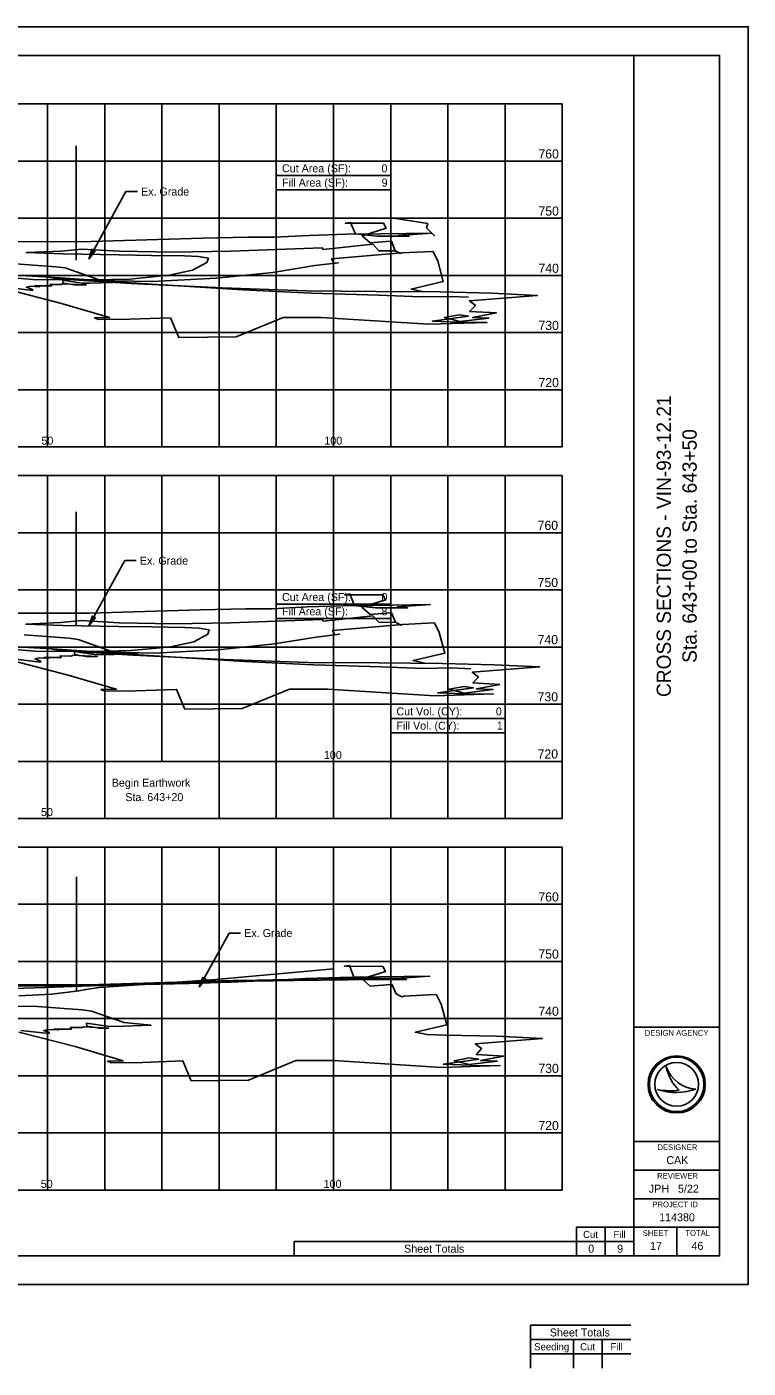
# Model space of a CAD drawing. Extents: x -46 to 154, y -27 to 78.
# Drawn here: x 116.94 to 129.55, y 54.21 to 77.68 of the extents above; entities that cross this region are included whole.
import ezdxf

# ---------------------------------------------------------------- set-up
doc = ezdxf.new("R2010")
doc.units = 0
for name, color, linetype in [('Default', 7, 'Continuous'), ('DT_P_Contour_Minor', 7, 'Continuous'), ('DT_X_Break_Line', 7, 'Continuous'), ('DT_X_Contour_Major', 7, 'Continuous'), ('DT_X_Contour_Minor', 7, 'Continuous'), ('DT_X_Spot_Elev', 7, 'Continuous'), ('DT_X_Void', 7, 'Continuous'), ('GE_P_Alignment_100_Stations', 7, 'Continuous'), ('HY_X_Water_Edge', 7, 'Continuous'), ('RD_X_Fence', 7, 'Continuous'), ('SH_Text', 7, 'Continuous'), ('XS_P_Pavt_Layers', 7, 'Continuous')]:
    doc.layers.add(name, color=color, linetype=linetype)

msp = doc.modelspace()

# ---------------------------------------------------------------- linework, layer by layer
at = {"layer": 'Default'}
for p, q in [((126.552, 56.178), (126.552, 56.678)), ((127.052, 56.178), (127.052, 56.678)), ((121.616, 56.178), (121.616, 56.428))]:
    msp.add_line(p, q, dxfattribs=at)
at = {"layer": 'DT_P_Contour_Minor'}
for p, q in [((118.674, 74.796), (118.022, 73.614)), ((118.874, 74.796), (118.674, 74.796)), ((118.022, 73.614), (118.085, 73.792)), ((118.138, 73.761), (118.022, 73.614)), ((118.085, 73.792), (118.085, 73.792)), ((118.138, 73.761), (118.138, 73.761)), ((118.655, 68.34), (118.026, 67.199)), ((118.855, 68.34), (118.655, 68.34)), ((118.026, 67.199), (118.089, 67.376)), ((118.142, 67.346), (118.026, 67.199)), ((118.089, 67.376), (118.089, 67.376)), ((118.142, 67.346), (118.142, 67.346)), ((120.478, 61.826), (119.956, 60.879)), ((120.678, 61.826), (120.478, 61.826)), ((119.956, 60.879), (120.018, 61.056)), ((120.072, 61.026), (119.956, 60.879)), ((120.018, 61.056), (120.018, 61.056)), ((120.072, 61.026), (120.072, 61.026))]:
    msp.add_line(p, q, dxfattribs=at)
for centre in [(118.135, 73.817), (118.139, 67.402), (120.068, 61.082)]:
    msp.add_arc(centre, 0.0563, 207.3099, 273.9906, dxfattribs=at)
at = {"layer": 'DT_X_Break_Line'}
for p, q in [((98.302, 76.328), (126.302, 76.328)), ((117.302, 70.328), (117.302, 76.328)), ((118.302, 70.328), (118.302, 76.328)), ((119.302, 70.328), (119.302, 76.328)), ((120.302, 70.328), (120.302, 76.328)), ((121.302, 70.328), (121.302, 76.328)), ((122.302, 70.328), (122.302, 76.328)), ((123.302, 70.328), (123.302, 76.328)), ((124.302, 70.328), (124.302, 76.328)), ((125.302, 70.328), (125.302, 76.328)), ((126.302, 70.328), (126.302, 76.328)), ((98.302, 75.328), (126.302, 75.328)), ((98.302, 74.328), (126.302, 74.328)), ((98.302, 73.328), (126.302, 73.328)), ((98.302, 72.328), (126.302, 72.328)), ((98.302, 71.328), (126.302, 71.328)), ((98.302, 70.328), (126.302, 70.328)), ((98.302, 69.828), (126.302, 69.828)), ((117.302, 63.828), (117.302, 69.828)), ((118.302, 63.828), (118.302, 69.828)), ((119.302, 64.828), (119.302, 69.828)), ((120.302, 63.828), (120.302, 69.828)), ((121.302, 63.828), (121.302, 69.828)), ((122.302, 63.828), (122.302, 69.828)), ((123.302, 63.828), (123.302, 69.828)), ((124.302, 63.828), (124.302, 69.828)), ((125.302, 63.828), (125.302, 69.828)), ((126.302, 63.828), (126.302, 69.828)), ((98.302, 68.828), (126.302, 68.828)), ((98.302, 67.828), (126.302, 67.828)), ((98.302, 66.828), (126.302, 66.828)), ((98.302, 65.828), (126.302, 65.828)), ((98.302, 64.828), (126.302, 64.828)), ((98.302, 63.828), (126.302, 63.828)), ((98.302, 63.328), (126.302, 63.328)), ((117.302, 57.328), (117.302, 63.328)), ((118.302, 57.328), (118.302, 63.328)), ((119.302, 57.328), (119.302, 63.328)), ((120.302, 57.328), (120.302, 63.328)), ((121.302, 57.328), (121.302, 63.328)), ((122.302, 57.328), (122.302, 63.328)), ((123.302, 57.328), (123.302, 63.328)), ((124.302, 57.328), (124.302, 63.328)), ((125.302, 57.328), (125.302, 63.328)), ((126.302, 57.328), (126.302, 63.328)), ((98.302, 62.328), (126.302, 62.328)), ((98.302, 61.328), (126.302, 61.328)), ((98.302, 60.328), (126.302, 60.328)), ((98.302, 59.328), (126.302, 59.328)), ((98.302, 58.328), (126.302, 58.328)), ((98.302, 57.328), (126.302, 57.328))]:
    msp.add_line(p, q, dxfattribs=at)
at = {"layer": 'DT_X_Contour_Major'}
msp.add_lwpolyline([(95.552, 55.678), (129.552, 55.678), (129.552, 77.678), (95.552, 77.678)], close=True, dxfattribs=at)
at = {"layer": 'DT_X_Contour_Minor'}
for p, q in [((121.302, 75.328), (123.302, 75.328)), ((121.302, 75.328), (121.302, 74.828)), ((123.302, 75.328), (123.302, 74.828)), ((121.302, 75.078), (123.302, 75.078)), ((121.302, 74.828), (123.302, 74.828)), ((121.302, 67.828), (123.302, 67.828)), ((121.302, 67.828), (121.302, 67.328)), ((123.302, 67.828), (123.302, 67.328)), ((121.302, 67.578), (123.302, 67.578)), ((121.302, 67.328), (123.302, 67.328)), ((123.302, 65.828), (125.302, 65.828)), ((123.302, 65.828), (123.302, 65.328)), ((125.302, 65.828), (125.302, 65.328)), ((123.302, 65.578), (125.302, 65.578)), ((123.302, 65.328), (125.302, 65.328)), ((128.119, 59.488), (128.119, 59.488)), ((128.119, 59.488), (128.119, 59.488)), ((128.302, 59.178), (128.302, 59.178)), ((127.969, 59.087), (127.969, 59.087)), ((127.969, 59.087), (127.969, 59.087)), ((128.639, 59.096), (128.639, 59.096)), ((128.639, 59.096), (128.639, 59.096)), ((126.552, 56.678), (127.552, 56.678)), ((128.302, 56.178), (128.302, 56.678)), ((121.616, 56.428), (127.552, 56.428)), ((125.749, 54.213), (125.749, 54.963)), ((125.749, 54.963), (127.499, 54.963)), ((125.749, 54.713), (127.499, 54.713)), ((126.499, 54.213), (126.499, 54.713)), ((126.999, 54.213), (126.999, 54.713)), ((125.749, 54.463), (127.499, 54.463)), ((126.131, 54.338), (126.131, 54.338)), ((126.754, 54.338), (126.754, 54.338)), ((127.259, 54.338), (127.259, 54.338))]:
    msp.add_line(p, q, dxfattribs=at)
for radius in [0.5, 0.5, 0.477, 0.477, 0.477, 0.477, 0.382, 0.382]:
    msp.add_circle((128.302, 59.178), radius, dxfattribs=at)
for centre, radius, start, end in [((128.668, 59.676), 0.58, 198.9257, 198.9319), ((128.898, 59.648), 0.796, 191.6379, 191.6421), ((128.668, 59.676), 0.58, 198.9257, 198.9319), ((128.898, 59.648), 0.796, 191.6379, 191.6421), ((128.668, 59.676), 0.58, 198.9319, 267.1657), ((128.898, 59.648), 0.796, 191.6421, 226.0947), ((128.668, 59.676), 0.58, 198.9319, 267.1657), ((128.898, 59.648), 0.796, 191.6421, 226.0947), ((128.291, 60.048), 1.013, 251.4576, 290.0832), ((128.291, 60.048), 1.013, 251.4576, 290.0832), ((128.2, 60.332), 1.266, 259.4964, 259.4995), ((128.291, 60.048), 1.013, 251.4527, 251.4576), ((128.2, 60.332), 1.266, 259.4995, 276.6672), ((128.2, 60.332), 1.266, 259.4964, 259.4995), ((128.291, 60.048), 1.013, 251.4527, 251.4576), ((128.2, 60.332), 1.266, 259.4995, 276.6672)]:
    msp.add_arc(centre, radius, start, end, dxfattribs=at)
at = {"layer": 'DT_X_Spot_Elev'}
for p, q in [((127.552, 56.178), (127.552, 77.178)), ((127.552, 60.178), (129.052, 60.178)), ((127.552, 58.178), (129.052, 58.178)), ((127.552, 57.678), (129.052, 57.678)), ((127.552, 57.178), (129.052, 57.178)), ((127.552, 56.678), (129.052, 56.678))]:
    msp.add_line(p, q, dxfattribs=at)
msp.add_lwpolyline([(97.052, 77.178), (129.052, 77.178), (129.052, 56.178), (97.052, 56.178)], close=True, dxfattribs=at)
at = {"layer": 'GE_P_Alignment_100_Stations'}
for p, q in [((117.802, 73.598), (117.802, 75.598)), ((117.805, 67.192), (117.805, 69.192)), ((117.809, 60.809), (117.809, 62.809))]:
    msp.add_line(p, q, dxfattribs=at)
at = {"layer": 'HY_X_Water_Edge'}
for points in [[(116.244, 73.328), (117.043, 73.257), (118.071, 73.25), (118.741, 73.265), (119.43, 73.333), (119.839, 73.421), (120.089, 73.553), (120.115, 73.631), (119.94, 73.658), (119.697, 73.671), (119.122, 73.679), (118.553, 73.69), (117.575, 73.706), (116.932, 73.728), (117.54, 73.756), (117.904, 73.79)], [(117.904, 73.79), (118.562, 73.754), (119.502, 73.736), (120.499, 73.752), (122.105, 73.81), (122.124, 73.781), (122.987, 73.874), (123.096, 73.76), (123.38, 73.761), (123.438, 73.728), (123.466, 73.712), (123.491, 73.723), (122.269, 73.618), (122.306, 73.543), (122.386, 73.552), (121.973, 73.5), (121.243, 73.383), (120.251, 73.281), (119.136, 73.22), (118.142, 73.243), (117.347, 73.29), (117.474, 73.27), (118.759, 73.187), (120.353, 73.11), (121.824, 73.06), (123.051, 73.05), (124.172, 73.041), (125.064, 73.02), (125.864, 72.98)], [(124.662, 72.949), (124.322, 72.962), (123.83, 72.955), (123.095, 72.982), (121.915, 73.017), (120.717, 73.076), (118.944, 73.185), (117.352, 73.299), (116.495, 73.343)], [(117.896, 67.29), (118.556, 67.254), (119.499, 67.236), (120.499, 67.252), (122.105, 67.31), (122.126, 67.281), (122.99, 67.374), (123.102, 67.26), (123.386, 67.261), (123.449, 67.228), (123.48, 67.212), (123.508, 67.223), (122.287, 67.118), (122.327, 67.043), (122.411, 67.052), (121.998, 67), (121.269, 66.883), (120.279, 66.781), (119.166, 66.72), (118.175, 66.743), (117.382, 66.79), (117.508, 66.77), (118.794, 66.687), (120.389, 66.61), (121.859, 66.56), (123.087, 66.55), (124.21, 66.541), (125.104, 66.52), (125.907, 66.48)], [(116.276, 66.828), (117.074, 66.757), (118.099, 66.75), (118.767, 66.765), (119.454, 66.833), (119.859, 66.921), (120.105, 67.053), (120.128, 67.131), (119.949, 67.158), (119.703, 67.171), (119.124, 67.179), (118.552, 67.19), (117.571, 67.206), (116.926, 67.228), (117.533, 67.256), (117.896, 67.29)], [(124.706, 66.449), (124.364, 66.462), (123.871, 66.455), (123.135, 66.482), (121.953, 66.517), (120.754, 66.576), (118.981, 66.685), (117.389, 66.799), (116.533, 66.843)], [(116.526, 60.904), (117.965, 60.9), (119.78, 60.945), (120.515, 60.966), (120.905, 60.982), (121.618, 60.994), (123.019, 61.015), (123.579, 61.014), (123.401, 61.029), (122.303, 61.028), (120.709, 60.996), (119.54, 60.947), (118.736, 60.917), (118.058, 60.904), (117.263, 60.872), (116.327, 60.843)], [(116.799, 60.728), (117.38, 60.756), (117.851, 60.813), (117.97, 60.838), (118.207, 60.874), (119.23, 60.943), (120.246, 61.012), (122.3, 61.2)]]:
    msp.add_lwpolyline(points, dxfattribs=at)
at = {"layer": 'RD_X_Fence'}
msp.add_lwpolyline([(123.315, 74.334), (123.95, 74.238), (123.929, 74.164), (124.076, 74.017)], dxfattribs=at)
at = {"layer": 'SH_Text'}
for points in [[(121.302, 75.328), (123.302, 75.328), (123.302, 74.828), (121.302, 74.828)], [(121.302, 67.828), (123.302, 67.828), (123.302, 67.328), (121.302, 67.328)], [(123.302, 65.828), (125.302, 65.828), (125.302, 65.328), (123.302, 65.328)]]:
    msp.add_lwpolyline(points, close=True, dxfattribs=at)
at = {"layer": 'XS_P_Pavt_Layers'}
for points in [[(116.653, 73.919), (118.066, 73.922), (120.01, 73.979), (120.804, 73.998), (121.264, 73.996), (121.875, 74.03), (122.684, 74.054), (123.066, 74.015), (123.623, 74.014), (123.441, 74.029), (124.019, 74.07), (122.688, 74.051), (122.602, 74.257), (122.51, 74.243), (123.176, 74.242), (123.221, 74.153), (122.801, 74.024), (122.943, 73.898), (123.3, 73.928), (123.314, 73.929), (123.38, 73.761), (123.438, 73.728), (123.466, 73.712), (123.491, 73.723), (124.031, 73.749), (124.046, 73.743), (124.127, 73.583), (124.222, 73.22), (123.659, 73.091), (123.861, 73.048), (124.172, 73.041), (125.064, 73.02), (125.864, 72.98), (124.679, 72.887), (124.784, 72.804), (124.682, 72.7), (125.149, 72.673), (124.734, 72.596), (125.016, 72.583), (124.511, 72.523), (124.241, 72.592), (124.501, 72.64), (124.662, 72.617), (124.031, 72.53), (124.493, 72.512), (124.548, 72.504), (124.988, 72.508), (123.963, 72.474), (122.088, 72.594), (121.422, 72.594), (120.598, 72.253), (119.598, 72.241), (119.451, 72.588), (118.743, 72.563), (118.196, 72.556), (118.126, 72.586), (118.386, 72.591), (117.549, 72.838), (116.56, 73.092)], [(116.565, 73.121), (117.043, 73.066), (117.041, 73.084), (116.932, 73.122), (117.006, 73.139), (117.163, 73.131), (117.078, 73.145), (117.372, 73.146), (117.346, 73.173), (117.541, 73.171), (117.558, 73.184), (117.978, 73.163), (117.813, 73.159), (117.574, 73.195), (117.562, 73.249), (117.91, 73.196), (118.03, 73.192), (118.65, 73.211), (118.185, 73.259), (117.611, 73.461), (117.45, 73.481), (116.667, 73.54)], [(116.62, 67.419), (118.033, 67.422), (119.978, 67.479), (120.772, 67.498), (121.23, 67.496), (121.84, 67.53), (122.648, 67.554), (123.04, 67.515), (123.598, 67.514), (123.418, 67.529), (123.998, 67.57), (122.671, 67.551), (122.59, 67.757), (122.499, 67.743), (123.166, 67.742), (123.214, 67.653), (122.799, 67.524), (122.941, 67.398), (123.3, 67.428), (123.316, 67.429), (123.386, 67.261), (123.449, 67.228), (123.48, 67.212), (123.508, 67.223), (124.054, 67.249), (124.071, 67.243), (124.152, 67.083), (124.25, 66.72), (123.694, 66.591), (123.898, 66.548), (124.21, 66.541), (125.104, 66.52), (125.907, 66.48), (124.727, 66.387), (124.835, 66.304), (124.74, 66.2), (125.21, 66.173), (124.801, 66.096), (125.088, 66.083), (124.589, 66.023), (124.323, 66.092), (124.586, 66.14), (124.749, 66.117), (124.124, 66.03), (124.591, 66.012), (124.65, 66.004), (125.097, 66.008), (124.072, 65.974), (122.196, 66.094), (121.531, 66.094), (120.705, 65.753), (119.705, 65.741), (119.558, 66.088), (118.849, 66.063), (118.302, 66.056), (118.237, 66.086), (118.503, 66.091), (117.665, 66.338), (116.677, 66.592)], [(116.698, 66.621), (117.181, 66.566), (117.185, 66.584), (117.081, 66.622), (117.161, 66.639), (117.323, 66.631), (117.243, 66.645), (117.543, 66.646), (117.522, 66.673), (117.723, 66.671), (117.745, 66.684), (118.171, 66.663), (118.011, 66.659), (117.778, 66.695), (117.771, 66.749), (118.125, 66.696), (118.249, 66.692), (118.877, 66.711), (118.411, 66.759), (117.837, 66.961), (117.677, 66.981), (116.894, 67.04)], [(116.592, 60.919), (118.006, 60.922), (119.951, 60.979), (120.745, 60.998), (121.202, 60.996), (121.81, 61.03), (122.619, 61.054), (123.019, 61.015), (123.579, 61.014), (123.401, 61.029), (123.983, 61.07), (122.66, 61.051), (122.584, 61.257), (122.494, 61.243), (123.162, 61.242), (123.213, 61.153), (122.802, 61.024), (122.946, 60.898), (123.305, 60.928), (123.324, 60.929), (123.397, 60.761), (123.464, 60.728), (123.499, 60.712), (123.531, 60.723), (124.082, 60.749), (124.102, 60.743), (124.183, 60.583), (124.284, 60.22), (123.734, 60.091), (123.94, 60.048), (124.254, 60.041), (125.15, 60.02), (125.955, 59.98), (124.78, 59.887), (124.892, 59.804), (124.802, 59.7), (125.278, 59.673), (124.873, 59.596), (125.165, 59.583), (124.672, 59.523), (124.411, 59.592), (124.676, 59.64), (124.842, 59.617), (124.223, 59.53), (124.693, 59.512), (124.757, 59.504), (125.211, 59.508), (124.186, 59.474), (122.31, 59.594), (121.646, 59.594), (120.817, 59.253), (119.816, 59.241), (119.669, 59.588), (118.961, 59.563), (118.413, 59.556), (118.353, 59.586), (118.624, 59.591), (117.787, 59.838), (116.798, 60.092)], [(116.837, 60.121), (117.325, 60.066), (117.334, 60.084), (117.236, 60.122), (117.321, 60.139), (117.489, 60.131), (117.414, 60.145), (117.719, 60.146), (117.704, 60.173), (117.91, 60.171), (117.938, 60.184), (118.37, 60.163), (118.214, 60.159), (117.987, 60.195), (117.986, 60.249), (118.345, 60.196), (118.474, 60.192), (119.109, 60.211), (118.643, 60.259), (118.07, 60.461), (117.909, 60.481), (117.126, 60.54), (115.911, 60.56)]]:
    msp.add_lwpolyline(points, dxfattribs=at)

# ---------------------------------------------------------------- texts
at = {"layer": 'Default'}
for s, height, p in [('Cut', 0.125, (126.666, 56.49)), ('Fill', 0.125, (127.196, 56.49)), ('Sheet Totals', 0.14, (123.537, 56.233)), ('0', 0.14, (126.756, 56.233)), ('9', 0.14, (127.261, 56.233))]:
    msp.add_text(s, height=height, dxfattribs=at).set_placement(p)
at = {"layer": 'DT_P_Contour_Minor'}
for p in [(118.937, 74.726), (118.918, 68.27), (120.741, 61.756)]:
    msp.add_text('Ex. Grade', height=0.14, dxfattribs=at).set_placement(p)
at = {"layer": 'DT_X_Contour_Minor'}
for s, p in [('CROSS SECTIONS - VIN-93-12.21', (128.202, 65.954)), ('Sta. 643+00 to Sta. 643+50', (128.652, 66.551))]:
    msp.add_text(s, height=0.25, rotation=90, dxfattribs=at).set_placement(p)
for s, height, p in [('DESIGN AGENCY', 0.1, (127.743, 60.028)), ('DESIGNER', 0.1, (127.966, 58.028)), ('CAK', 0.14, (128.121, 57.783)), ('REVIEWER', 0.1, (127.961, 57.528)), ('JPH   5/22', 0.14, (127.815, 57.283)), ('PROJECT ID', 0.1, (127.877, 57.028)), ('114380', 0.14, (127.996, 56.783)), ('SHEET', 0.1, (127.709, 56.528)), ('TOTAL', 0.1, (128.454, 56.528)), ('17', 0.14, (127.837, 56.283)), ('46', 0.14, (128.561, 56.283)), ('Sheet Totals', 0.14, (126.084, 54.768)), ('Seeding', 0.125, (125.81, 54.526)), ('Cut', 0.125, (126.614, 54.526)), ('Fill', 0.125, (127.144, 54.526))]:
    msp.add_text(s, height=height, dxfattribs=at).set_placement(p)
at = {"layer": 'DT_X_Void'}
for s, height, p in [('760', 0.16, (125.886, 75.375)), ('Cut Area (SF):', 0.14, (121.402, 75.133)), ('0', 0.14, (123.141, 75.133)), ('Fill Area (SF):', 0.14, (121.402, 74.883)), ('9', 0.14, (123.144, 74.883)), ('750', 0.16, (125.886, 74.375)), ('740', 0.16, (125.886, 73.375)), ('730', 0.16, (125.886, 72.375)), ('720', 0.16, (125.886, 71.375)), ('50', 0.14, (117.196, 70.369)), ('100', 0.14, (122.142, 70.369)), ('760', 0.16, (125.871, 68.878)), ('750', 0.16, (125.871, 67.878)), ('Cut Area (SF):', 0.14, (121.402, 67.633)), ('0', 0.14, (123.141, 67.633)), ('Fill Area (SF):', 0.14, (121.402, 67.383)), ('8', 0.14, (123.141, 67.383)), ('740', 0.16, (125.871, 66.878)), ('730', 0.16, (125.871, 65.878)), ('Cut Vol. (CY):', 0.14, (123.402, 65.633)), ('0', 0.14, (125.141, 65.633)), ('Fill Vol. (CY):', 0.14, (123.402, 65.383)), ('1', 0.14, (125.158, 65.383)), ('100', 0.14, (122.134, 64.871)), ('720', 0.16, (125.871, 64.878)), ('Begin Earthwork', 0.14, (118.425, 64.385)), ('Sta. 643+20', 0.14, (118.662, 64.133)), ('50', 0.14, (117.189, 63.871)), ('760', 0.16, (125.884, 62.378)), ('750', 0.16, (125.884, 61.378)), ('740', 0.16, (125.884, 60.378)), ('730', 0.16, (125.884, 59.378)), ('720', 0.16, (125.884, 58.378)), ('50', 0.14, (117.184, 57.368)), ('100', 0.14, (122.13, 57.368))]:
    msp.add_text(s, height=height, dxfattribs=at).set_placement(p)

doc.saveas('drawing.dxf')
